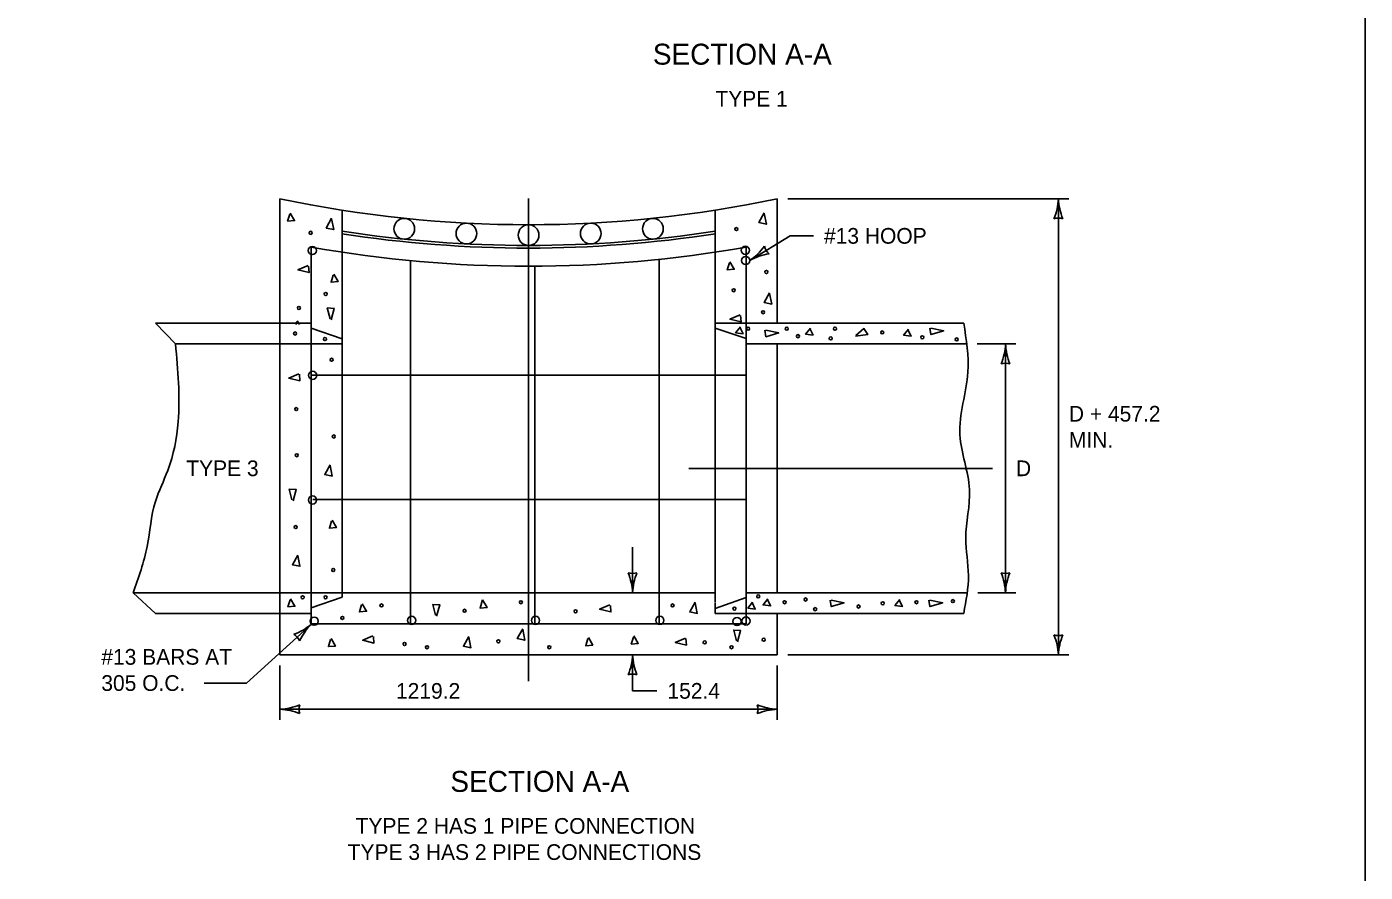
# Model space of a CAD drawing. Extents: x 49991.4 to 50021, y 49987.6 to 50011.4.
# Drawn here: x 50011.64 to 50016.75, y 49992.82 to 49996.05 of the extents above; entities that cross this region are included whole.
import ezdxf

# ---------------------------------------------------------------- set-up
doc = ezdxf.new("R2010")
doc.units = 0
for name, color, linetype in [('Level 1', 7, 'Continuous'), ('Level 2', 7, 'Continuous'), ('Level 3', 7, 'Continuous'), ('Level 4', 7, 'Continuous'), ('Level 5', 7, 'Continuous')]:
    doc.layers.add(name, color=color, linetype=linetype)

msp = doc.modelspace()

# ---------------------------------------------------------------- linework, layer by layer
at = {"layer": 'Level 1'}
for p, q in [((50012.6035, 49995.3966), (50012.6035, 49994.9216)), ((50014.5035, 49995.3966), (50014.5035, 49994.9216)), ((50012.841, 49993.8924), (50012.841, 49995.353)), ((50014.2661, 49993.8544), (50014.2661, 49995.353)), ((50012.7222, 49993.7737), (50012.7222, 49995.2124)), ((50014.3847, 49994.8424), (50014.3847, 49995.2123)), ((50013.1022, 49993.7737), (50013.1022, 49995.1608)), ((50013.5772, 49993.7737), (50013.5772, 49995.1394)), ((50014.0522, 49993.7737), (50014.0522, 49995.1655)), ((50012.6035, 49994.9216), (50012.6035, 49993.8133)), ((50014.2661, 49994.9216), (50015.216, 49994.9216)), ((50014.2661, 49994.9025), (50014.3848, 49994.863)), ((50014.3848, 49994.863), (50014.3848, 49994.8424)), ((50014.3848, 49994.8424), (50015.2272, 49994.8425)), ((50014.3848, 49994.3859), (50014.3848, 49994.8424)), ((50012.7272, 49994.7237), (50014.3848, 49994.7237)), ((50014.3848, 49993.8949), (50014.3848, 49994.3859)), ((50012.7289, 49994.2487), (50014.3848, 49994.2487)), ((50012.841, 49993.8924), (50014.2661, 49993.8924)), ((50014.3847, 49993.7737), (50014.3847, 49993.8924)), ((50014.3848, 49993.894), (50014.3848, 49993.8734)), ((50014.3848, 49993.8924), (50015.2259, 49993.8924)), ((50014.3848, 49993.8924), (50014.3848, 49993.8734)), ((50014.2661, 49993.8323), (50014.3848, 49993.8734)), ((50014.2661, 49993.8529), (50014.2661, 49993.8133)), ((50012.6035, 49993.6549), (50012.6035, 49993.8133)), ((50014.2661, 49993.8133), (50015.216, 49993.8133)), ((50014.5035, 49993.6549), (50014.5035, 49993.8133)), ((50012.7222, 49993.7737), (50014.3848, 49993.7737)), ((50012.6035, 49993.6549), (50014.5035, 49993.6549))]:
    msp.add_line(p, q, dxfattribs=at)
msp.add_lwpolyline([(49999.3835, 49998.9992), (50016.7501, 49998.9992), (50016.7501, 49987.7988), (49999.3835, 49987.7988)], close=True, dxfattribs=at)
for points in [[(50012.6411, 49995.3383), (50012.6329, 49995.3115), (50012.6597, 49995.3138), (50012.6431, 49995.3424)], [(50014.4538, 49995.3426), (50014.4334, 49995.3056), (50014.462, 49995.2995), (50014.4538, 49995.3406)], [(50012.8009, 49995.3222), (50012.7804, 49995.2852), (50012.8091, 49995.279), (50012.8009, 49995.3201)], [(50012.7108, 49995.1418), (50012.6719, 49995.1254), (50012.7149, 49995.1149), (50012.7128, 49995.1397)], [(50014.3206, 49995.1519), (50014.3123, 49995.1251), (50014.3391, 49995.1274), (50014.3226, 49995.156)], [(50012.807, 49995.1049), (50012.7988, 49995.0781), (50012.8256, 49995.0804), (50012.8091, 49995.109)], [(50014.4742, 49995.0375), (50014.4538, 49995.0005), (50014.4824, 49994.9944), (50014.4742, 49995.0354)], [(50012.7948, 49994.9389), (50012.7845, 49994.9799), (50012.811, 49994.9778), (50012.7988, 49994.9349)], [(50012.6676, 49994.9267), (50012.6645, 49994.9167)], [(50012.6778, 49994.9167), (50012.6697, 49994.9308)], [(50014.3616, 49994.9534), (50014.3228, 49994.9369), (50014.3656, 49994.9265), (50014.3636, 49994.9513)], [(50014.3628, 49994.908), (50014.3445, 49994.8854), (50014.3731, 49994.8813), (50014.3609, 49994.906)], [(50014.46, 49994.8945), (50014.5092, 49994.8844), (50014.46, 49994.87), (50014.4559, 49994.8945)], [(50014.63, 49994.903), (50014.6116, 49994.8803), (50014.6402, 49994.8763), (50014.628, 49994.9009)], [(50014.8041, 49994.8742), (50014.835, 49994.9009), (50014.8493, 49994.8782), (50014.802, 49994.8721)], [(50015.0048, 49994.8989), (50014.9864, 49994.8762), (50015.0149, 49994.8721), (50015.0028, 49994.8969)], [(50015.0908, 49994.9028), (50015.14, 49994.8925), (50015.0908, 49994.8782), (50015.0868, 49994.9028)], [(50012.6759, 49994.7286), (50012.637, 49994.7123), (50012.68, 49994.7019), (50012.6779, 49994.7265)], [(50012.7949, 49994.3806), (50012.7745, 49994.3436), (50012.8029, 49994.3375), (50012.7949, 49994.3786)], [(50012.6493, 49994.2473), (50012.6391, 49994.2882), (50012.6656, 49994.2861), (50012.6534, 49994.2432)], [(50012.8008, 49994.1654), (50012.7925, 49994.1386), (50012.8194, 49994.1409), (50012.8029, 49994.1695)], [(50012.6718, 49994.0362), (50012.6514, 49993.9992), (50012.68, 49993.9931), (50012.6718, 49994.0342)], [(50012.642, 49993.8653), (50012.6337, 49993.8385), (50012.6605, 49993.8408), (50012.644, 49993.8694)], [(50012.9156, 49993.8457), (50012.9074, 49993.8189), (50012.9343, 49993.8212), (50012.9177, 49993.8499)], [(50013.1983, 49993.8069), (50013.188, 49993.8478), (50013.2146, 49993.8457), (50013.2023, 49993.8029)], [(50013.3779, 49993.865), (50013.3682, 49993.8333), (50013.3951, 49993.8355), (50013.3779, 49993.865)], [(50013.8638, 49993.8458), (50013.825, 49993.8294), (50013.868, 49993.8189), (50013.8659, 49993.8438)], [(50014.1896, 49993.8562), (50014.1692, 49993.8192), (50014.1977, 49993.8131), (50014.1896, 49993.8542)], [(50014.4096, 49993.8564), (50014.3912, 49993.8337), (50014.4198, 49993.8297), (50014.4076, 49993.8544)], [(50014.4681, 49993.8684), (50014.4497, 49993.8457), (50014.4783, 49993.8417), (50014.4661, 49993.8664)], [(50014.7099, 49993.8641), (50014.7591, 49993.8539), (50014.7099, 49993.8396), (50014.7059, 49993.8641)], [(50014.9719, 49993.8664), (50014.9534, 49993.8438), (50014.982, 49993.8396), (50014.9699, 49993.8644)], [(50015.0867, 49993.8641), (50015.1359, 49993.8539), (50015.0867, 49993.8396), (50015.0827, 49993.8641)], [(50013.531, 49993.7539), (50013.5105, 49993.7169), (50013.5391, 49993.7107), (50013.531, 49993.7518)], [(50014.3474, 49993.7086), (50014.3371, 49993.7494), (50014.3637, 49993.7474), (50014.3514, 49993.7045)], [(50012.7972, 49993.7132), (50012.7889, 49993.6863), (50012.8157, 49993.6886), (50012.7992, 49993.7172)], [(50012.9584, 49993.727), (50012.9197, 49993.7107), (50012.9626, 49993.7002), (50012.9605, 49993.725)], [(50013.3252, 49993.725), (50013.3048, 49993.688), (50013.3333, 49993.6819), (50013.3252, 49993.7229)], [(50013.7798, 49993.7168), (50013.7717, 49993.69), (50013.7985, 49993.6923), (50013.7819, 49993.7209)], [(50013.954, 49993.7229), (50013.9458, 49993.6962), (50013.9727, 49993.6984), (50013.9561, 49993.727)], [(50014.1526, 49993.7189), (50014.1138, 49993.7025), (50014.1566, 49993.692), (50014.1546, 49993.7169)]]:
    msp.add_lwpolyline(points, dxfattribs=at)
for centre in [(50012.7211, 49995.2668), (50014.3473, 49995.2811), (50014.4619, 49995.1172), (50012.7784, 49995.0332), (50014.3371, 49995.0475), (50012.6759, 49994.9798), (50014.4497, 49994.9635), (50012.6616, 49994.8823), (50012.7754, 49994.8612), (50014.3924, 49994.9007), (50014.5399, 49994.9007), (50014.5828, 49994.8721), (50014.7079, 49994.8637), (50014.7242, 49994.9007), (50014.9045, 49994.8864), (50015.0579, 49994.8678), (50015.1891, 49994.8596), (50012.801, 49994.782), (50012.6658, 49994.5936), (50012.8092, 49994.4889), (50012.6678, 49994.4174), (50012.6637, 49994.1429), (50012.8071, 49993.979), (50012.6902, 49993.8748), (50012.7777, 49993.8749), (50012.9915, 49993.8437), (50013.524, 49993.856), (50014.1036, 49993.8437), (50014.4308, 49993.8784), (50014.5317, 49993.856), (50014.6116, 49993.8664), (50014.8143, 49993.8396), (50014.9065, 49993.8519), (50015.0355, 49993.856), (50015.1748, 49993.8601), (50012.8419, 49993.796), (50013.3088, 49993.8233), (50013.7329, 49993.8213), (50014.3401, 49993.8314), (50014.6484, 49993.8294), (50013.0796, 49993.6964), (50013.1656, 49993.6841), (50013.438, 49993.7066), (50013.6325, 49993.6841), (50014.2264, 49993.7025), (50014.3288, 49993.6841), (50014.4518, 49993.7127)]:
    msp.add_circle(centre, 0.00579, dxfattribs=at)
for major_axis, start_param, end_param in [((0, -4.6095), 6.075593, 6.490779), ((0, -4.6886), 6.13064, 6.435748), ((0, -4.6985), 6.130631, 6.435739), ((0, -4.7678), 6.107927, 6.458424)]:
    msp.add_ellipse((50013.5535, 49999.9071), major_axis=major_axis, ratio=0.99996, start_param=start_param, end_param=end_param, dxfattribs=at)
for centre, major_axis in [((50013.0785, 49995.2822), (0, 0.0396)), ((50013.316, 49995.2641), (0, 0.0396)), ((50013.5535, 49995.2581), (0, 0.0396)), ((50013.791, 49995.2641), (0, 0.0396)), ((50014.0285, 49995.2822), (0, 0.0396)), ((50012.7275, 49995.1995), (0, 0.0156)), ((50014.3815, 49995.2), (0, 0.0156)), ((50014.3831, 49995.1609), (0, 0.0156)), ((50012.7288, 49994.7223), (0, 0.0156)), ((50012.728, 49994.2466), (0, 0.0156)), ((50012.7341, 49993.7837), (0, 0.0156)), ((50013.1068, 49993.7866), (0, 0.0156)), ((50013.5798, 49993.7866), (0, 0.0156)), ((50014.055, 49993.7866), (0, 0.0156)), ((50014.3498, 49993.7825), (0, 0.0156)), ((50014.384, 49993.7841), (0, 0.0156))]:
    msp.add_ellipse(centre, major_axis=major_axis, ratio=0.99996, dxfattribs=at)
msp.add_spline([(50015.216, 49994.9216), (50015.232, 49994.7348), (50015.2014, 49994.495), (50015.2381, 49994.2861), (50015.2239, 49994.0998), (50015.2341, 49993.9585), (50015.216, 49993.8133)], degree=3, dxfattribs=at)
at = {"layer": 'Level 3'}
for p, q in [((50014.5435, 49995.3966), (50015.6177, 49995.3966)), ((50015.5777, 49993.6549), (50015.5777, 49995.3966)), ((50014.3987, 49995.1615), (50014.5526, 49995.2552)), ((50014.5526, 49995.2552), (50014.6422, 49995.2552)), ((50015.2672, 49994.8425), (50015.4157, 49994.8424)), ((50015.3757, 49993.8924), (50015.3757, 49994.8424)), ((50013.9509, 49993.8924), (50013.9509, 49994.0658)), ((50015.2697, 49993.8924), (50015.4157, 49993.8924)), ((50012.4763, 49993.5473), (50012.7237, 49993.7721)), ((50013.9509, 49993.6549), (50013.9509, 49993.5174)), ((50014.5435, 49993.6549), (50015.6177, 49993.6549)), ((50012.6035, 49993.6149), (50012.6035, 49993.4072)), ((50014.5035, 49993.6149), (50014.5035, 49993.4072)), ((50012.3142, 49993.5473), (50012.4763, 49993.5473)), ((50013.9509, 49993.5174), (50014.0441, 49993.5174)), ((50012.6035, 49993.4472), (50014.5035, 49993.4472))]:
    msp.add_line(p, q, dxfattribs=at)
for centre, radius, start, end in [((50014.2678, 49995.3542), 0.233, 304.168, 323.4179), ((50014.5064, 49994.967), 0.2223, 98.7967, 118.9802), ((50014.5082, 49995.2281), 0.0548, 193.4795, 229.2019), ((50012.5811, 49993.9427), 0.2223, 289.7159, 309.8994), ((50012.8887, 49993.6076), 0.233, 135.0872, 154.337), ((50012.6288, 49993.6859), 0.0548, 24.3987, 60.121)]:
    msp.add_arc(centre, radius, start, end, dxfattribs=at)
for centre, major_axis, start_param, end_param in [((50015.3556, 49995.4058), (0, -0.2223), 1.177329, 1.529598), ((50015.8104, 49995.4081), (0, -0.233), 4.761735, 5.097708), ((50015.5777, 49995.2684), (0, 0.0548), 5.971449, 6.594922), ((50015.1536, 49994.8516), (0, -0.2223), 1.177329, 1.529598), ((50015.6084, 49994.8539), (0, -0.233), 4.761735, 5.097708), ((50015.3757, 49994.7142), (0, 0.0548), 5.971449, 6.594922), ((50013.9509, 49994.0206), (0, -0.0548), 5.971449, 6.594922), ((50013.7182, 49993.8809), (0, 0.233), 4.761735, 5.097708), ((50014.173, 49993.8832), (0, 0.2223), 1.177329, 1.529598), ((50015.3757, 49994.0206), (0, -0.0548), 5.971449, 6.594922), ((50015.143, 49993.8809), (0, 0.233), 4.761735, 5.097708), ((50015.5978, 49993.8832), (0, 0.2223), 1.177329, 1.529598), ((50015.5777, 49993.7831), (0, -0.0548), 5.971449, 6.594922), ((50015.345, 49993.6434), (0, 0.233), 4.761735, 5.097708), ((50015.7998, 49993.6457), (0, 0.2223), 1.177329, 1.529598), ((50013.7288, 49993.6641), (0, -0.2223), 1.177329, 1.529598), ((50014.1836, 49993.6664), (0, -0.233), 4.761735, 5.097708), ((50013.9509, 49993.5267), (0, 0.0548), 5.971449, 6.594922), ((50012.592, 49993.6799), (0, -0.233), 0.049346, 0.385319), ((50012.5943, 49993.2251), (0, 0.2223), 5.889718, 6.241987), ((50012.7317, 49993.4472), (0, 0.0548), 1.25906, 1.882533), ((50014.5127, 49993.6693), (0, -0.2223), 5.889718, 6.241987), ((50014.3753, 49993.4472), (0, -0.0548), 1.25906, 1.882533), ((50014.515, 49993.2145), (0, 0.233), 0.049346, 0.385319)]:
    msp.add_ellipse(centre, major_axis=major_axis, ratio=0.99996, start_param=start_param, end_param=end_param, dxfattribs=at)
at = {"layer": 'Level 4'}
for p, q in [((50012.1286, 49994.9216), (50012.7223, 49994.9216)), ((50012.2043, 49994.8424), (50012.1286, 49994.9216)), ((50012.7223, 49994.9216), (50012.7223, 49994.9026)), ((50012.7223, 49994.9026), (50012.841, 49994.8614)), ((50012.2043, 49994.8424), (50012.841, 49994.8424)), ((50014.5035, 49994.8424), (50014.5035, 49993.8924)), ((50012.0432, 49993.8924), (50012.841, 49993.8924)), ((50012.1286, 49993.8133), (50012.0432, 49993.8924)), ((50012.841, 49993.8924), (50012.841, 49993.875)), ((50012.7223, 49993.8339), (50012.841, 49993.875)), ((50012.1286, 49993.8133), (50012.7223, 49993.8133)), ((50012.7223, 49993.8339), (50012.7223, 49993.8133))]:
    msp.add_line(p, q, dxfattribs=at)
msp.add_spline([(50012.2043, 49994.8424), (50012.2146, 49994.5444), (50012.1751, 49994.3595), (50012.1276, 49994.2408), (50012.096, 49994.0691), (50012.0432, 49993.8924)], degree=3, dxfattribs=at)
at = {"layer": 'Level 5'}
for p, q in [((50013.5534, 49995.3976), (50013.5535, 49993.5549)), ((50015.3259, 49994.3671), (50014.1661, 49994.3671))]:
    msp.add_line(p, q, dxfattribs=at)

# ---------------------------------------------------------------- texts
at = {"layer": 'Level 2'}
for s, height, p in [('SECTION A-A', 0.08, (50014.0283, 49995.9091)), ('TYPE 1', 0.06, (50014.2674, 49995.7491)), ('#13 HOOP', 0.06, (50014.6822, 49995.2252)), ('D + 457.2', 0.06, (50015.6177, 49994.5458)), ('MIN.', 0.06, (50015.6177, 49994.4457)), ('TYPE 3', 0.06, (50012.2456, 49994.3375)), ('D', 0.06, (50015.4157, 49994.3374)), ('#13 BARS AT', 0.06, (50011.921, 49993.6173)), ('305 O.C.', 0.06, (50011.921, 49993.5173)), ('1219.2', 0.06, (50013.0469, 49993.4872)), ('152.4', 0.06, (50014.0841, 49993.4874)), ('SECTION A-A', 0.08, (50013.2546, 49993.1316)), ('TYPE 2 HAS 1 PIPE CONNECTION ', 0.06, (50012.8926, 49992.9716)), ('TYPE 3 HAS 2 PIPE CONNECTIONS', 0.06, (50012.8623, 49992.8716))]:
    msp.add_text(s, height=height, dxfattribs=at).set_placement(p)

doc.saveas('drawing.dxf')
